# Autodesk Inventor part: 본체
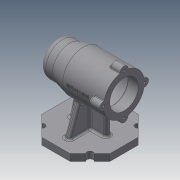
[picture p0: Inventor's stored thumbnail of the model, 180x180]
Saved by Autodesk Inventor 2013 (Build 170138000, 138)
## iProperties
Created: 2021-01
Part Number: 본체
Material: Generic
Document SubType Name: Modeling
Designer: user
Density: 1 g/cm^3
Author: user
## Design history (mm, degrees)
sketch "스케치1"
  geometry: L1 (0, 0)-(100, 0); L2 (100, 0)-(100, 30); L3 (100, 30)-(40, 30); L4 (40, 30)-(20, 25); L5 (20, 25)-(0, 25); L6 (0, 25)-(0, 0)
  constraints: 12 end point, 2 parallel, 2 perpendicular, 1 horizontal
  dimensions: "d0" = 100 distance of L1.start L1.end; "d1" = 60 diameter of L3 L1; "d2" = 50 diameter of L5 L1; "d3" = 20 distance of L5.end L4.end; "d4" = 40 horizontal distance of L5.end L3.end
revolve "회전1" sketch "스케치1" stored, may be unused: angle "d5" = 90 deg
sketch "스케치2"
  geometry: L1 (0, -25)-(0, 25) reference; L2 (0, 25)-(20, 25) reference; L3 (20, 25)-(40, 30) reference; L4 (40, 30)-(100, 30) reference; L5 (100, 30)-(100, -30) reference; L6 (100, -30)-(40, -30) reference; L7 (40, -30)-(20, -25) reference; L8 (20, -25)-(0, -25) reference; L9 (100, 0)-(6, 0); L10 (100, 0)-(100, 21); L11 (100, 21)-(85, 21); L12 (85, 21)-(85, 24); L13 (85, 24)-(43, 24); L14 (43, 24)-(43, 21); L15 (43, 21)-(31, 21); L16 (31, 21)-(31, 17.5); L17 (31, 17.5)-(13, 17.5); L18 (13, 17.5)-(13, 16); L19 (13, 16)-(9, 16); L20 (9, 16)-(9, 10.5); L21 (9, 10.5)-(6, 10.5); L22 (6, 10.5)-(6, 0); 1 further point
  constraints: 28 end point, 9 parallel, 4 perpendicular, 1 collinear, 1 midpoint, 1 point on line
  dimensions: "d6" = 42 diameter of L11 L9; "d8" = 48 diameter of L13 L9; "d9" = 21 diameter of L21 L9; "d10" = 32 diameter of L19 L9; "d11" = 35 diameter of L17 L9; "d12" = 42 diameter of L15 L9; "d13" = 15 distance of L10.end L11.end; "d14" = 42 distance of L12.end L13.end; "d15" = 12 distance of L14.end L15.end; "d16" = 18 distance of L16.end L17.end; "d17" = 4 distance of L18.end L19.end; "d18" = 3 distance of L20.end L21.end
revolve "회전2" sketch "스케치2" stored, may be unused: angle "d19" = 90 deg
fillet "모깎기1" dims "d20" = 0.3
fillet "모깎기2" dims "d21" = 10
sketch "스케치3"
  geometry: C1 r 6 at (0, 30); 1 further point
  constraints: 1 centre point, 1 vertical alignment, 1 other
  dimensions: "d22" = 6 radius of C1
extrude "돌출1" join sketch "스케치3" distance "d23" = 16; taper "d24" = 0 deg
sketch "스케치4"
  geometry: A1 r 6 centre (0, 0) between (5.97, -0.6) and (-5.97, -0.6) reference; 1 further point
  constraints: 1 coincident
hole "구멍1" sketch "스케치4" at (0, 0) diameter "d25" = 3.242; stored, may be unused: countersink angle "d29" = 90 deg, drill point angle "d31" = 118 deg; dims "d26" = 8, "d27" = 4, "d28" = 2, "d30" = 10
node "작업 평면1"
sketch "스케치5" dims "d36" = 50
  geometry: L1 (-100, -6)-(-100, 6) reference; L2 (-70.711, -50)-(-100, -20.711); L3 (-100, -20.711)-(-100, 20.711); L4 (-100, 20.711)-(-70.711, 50); L5 (-70.711, 50)-(-29.289, 50); L6 (-29.289, 50)-(0, 20.711); L7 (0, 20.711)-(0, -20.711); L8 (0, -20.711)-(-29.289, -50); L9 (-29.289, -50)-(-70.711, -50); 6 further points
  constraints: 16 end point, 2 vertical alignment, 1 coincident, 1 horizontal alignment, 1 midpoint, 1 vertical, 19 other
extrude "돌출2" join sketch "스케치5" distance "d37" = 10; taper "d38" = 0 deg
sketch "스케치7"
  geometry: L1 (100, 20.711)-(70.711, 50) reference; L2 (29.289, 50)-(0, 20.711) reference; L3 (0, -20.711)-(29.289, -50) reference; L4 (70.711, -50)-(100, -20.711) reference; 5 further points
  constraints: 4 midpoint
hole "구멍2" sketch "스케치7" at (14.645, 35.355), (14.645, -35.355), (85.355, -35.355), (85.355, 35.355) diameter "d42" = 9; stored, may be unused: countersink angle "d46" = 90 deg, drill point angle "d48" = 118 deg; dims "d43" = 8, "d44" = 4, "d45" = 2, "d47" = 10
sketch "스케치8"
  geometry: L1 (100, -20.711)-(100, 20.711) reference; L2 (0, 20.711)-(0, -20.711) reference; L3 (23, 4)-(77, 4); L4 (77, 4)-(77, -4); L5 (77, -4)-(23, -4); L6 (23, -4)-(23, 4); 3 further points
  constraints: 8 end point, 2 midpoint, 2 parallel, 1 horizontal, 1 horizontal alignment, 1 perpendicular
  dimensions: "d49" = 8 distance between parallel lines of L3 L5; "d51" = 23 distance between parallel lines of L1 L4; "d52" = 23 distance between parallel lines of L2 L6
extrude "돌출4" join sketch "스케치8" stored distance "d53" = 10; taper "d54" = 0 deg
feature "면 기울기1" dims angle "d55" = 11 deg
node "작업 평면2"
sketch "스케치9"
  geometry: L1 (-75, -50)-(-75, 50) reference; L2 (-75, 50)-(-65, 50) reference; L3 (-65, 50)-(-65, 4) reference; L4 (-65, 4)-(-29.732, 4) reference; L5 (-29.732, -4)-(-65, -4) reference; L6 (-65, -4)-(-65, -50) reference; L7 (-65, -50)-(-75, -50) reference; L8 (-65, 35)-(-22.707, 19.606); C1 r 24 at (0, 0) reference; A1 r 30 centre (0, 0) between (-29.732, -4) and (-29.732, 4) reference; 1 further point
  constraints: 2 end point, 1 point on circle, 1 point on line
  dimensions: "d57" = 15 distance from line of L2 L8.start; "d58" = 110 deg angle of L8 L3
feature "리브1" sketch "스케치9" dims "d59" = 1, "d60" = 8, "d61" = 0, "d62" = 0, "d63" = 1, "d64" = 1
fillet "모깎기3" dims "d65" = 3
fillet "모깎기4" dims "d66" = 1
fillet "모깎기5" dims "d67" = 3
fillet "모깎기6" dims "d68" = 3
node "작업 평면3"
sketch "스케치10"
  geometry: L1 (100, 36)-(100, 30.171) reference; 2 further points
  constraints: 1 horizontal alignment, 1 other
  dimensions: "d70" = 38 distance from line of L1 point (62, 0)
feature "엠보싱1" sketch "스케치10" dims "d0" = 100, "d1" = 60, "d2" = 50, "d3" = 20, "d4" = 40, "d71" = 0.5, "d72" = 0
node "솔리드1"
pattern_circular "원형 패턴1" dims angle "d33" = 360 deg
mirror "대칭1"
node "절단 모서리 투영1"
node "절단 모서리 투영2"
other parameters: "d35" = -75
